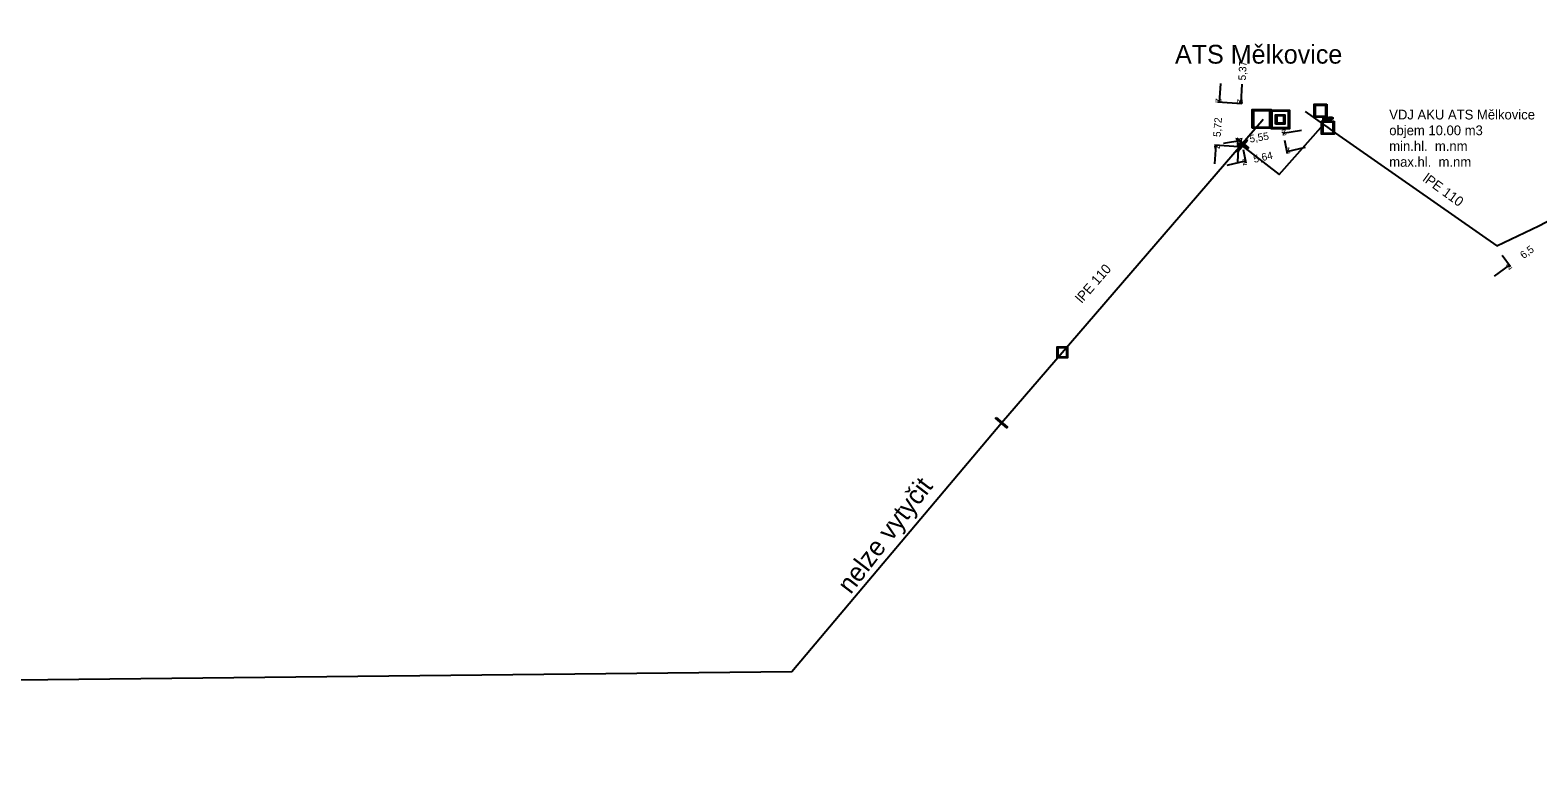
# Model space of a CAD drawing. Extents: x -638315 to -636370, y -1116147 to -1115110.
# Drawn here: x -638032 to -637831.1, y -1115501.1 to -1115402.4 of the extents above; entities that cross this region are included whole.
import ezdxf

# ---------------------------------------------------------------- set-up
doc = ezdxf.new("R2010")
doc.units = 0
for name, color, linetype in [('Default', 7, 'Continuous'), ('VP Kótování', 7, 'Continuous'), ('VP Popis nerozlišený', 7, 'Continuous'), ('VP Vodojem', 7, 'Continuous'), ('VP Vodojem - popis', 7, 'Continuous'), ('VP Čerpací stanice', 7, 'Continuous'), ('VP Řad', 7, 'Continuous'), ('VP Řad - popis', 7, 'Continuous'), ('VP Šachta', 7, 'Continuous'), ('VP Šoupě', 7, 'Continuous')]:
    doc.layers.add(name, color=color, linetype=linetype)

msp = doc.modelspace()

# ---------------------------------------------------------------- linework, layer by layer
at = {"layer": 'Default'}
for points in [[(-637859.55, -1115414.05), (-637859.5, -1115414.05), (-637859.48, -1115414.05), (-637859.45, -1115414.06), (-637859.43, -1115414.07), (-637859.4, -1115414.09), (-637859.39, -1115414.11), (-637859.38, -1115414.14), (-637859.38, -1115414.17), (-637859.38, -1115414.23), (-637859.41, -1115414.26), (-637859.45, -1115414.3), (-637859.54, -1115414.3)], [(-637859.54, -1115414.25), (-637859.48, -1115414.25), (-637859.46, -1115414.23), (-637859.44, -1115414.21), (-637859.44, -1115414.17), (-637859.44, -1115414.15), (-637859.45, -1115414.13), (-637859.46, -1115414.11), (-637859.49, -1115414.1), (-637859.5, -1115414.1), (-637859.54, -1115414.1)], [(-637859.07, -1115414.39), (-637859.1, -1115414.35), (-637859.11, -1115414.33), (-637859.13, -1115414.31), (-637859.14, -1115414.3), (-637859.16, -1115414.29), (-637859.17, -1115414.29), (-637859.18, -1115414.28), (-637859.2, -1115414.28)], [(-637859.14, -1115414.24), (-637859.1, -1115414.24), (-637859.08, -1115414.23), (-637859.06, -1115414.22), (-637859.05, -1115414.2), (-637859.04, -1115414.19), (-637859.04, -1115414.16), (-637859.04, -1115414.13), (-637859.06, -1115414.11), (-637859.08, -1115414.09), (-637859.13, -1115414.09)], [(-637859.13, -1115414.05), (-637859.08, -1115414.05), (-637859.05, -1115414.06), (-637859.02, -1115414.07), (-637859, -1115414.1), (-637858.98, -1115414.13), (-637858.98, -1115414.16), (-637858.98, -1115414.21), (-637859.01, -1115414.24), (-637859.04, -1115414.27), (-637859.1, -1115414.28), (-637859.08, -1115414.29), (-637859.07, -1115414.3), (-637859.04, -1115414.32), (-637859.02, -1115414.36)], [(-637858.58, -1115414.05), (-637858.54, -1115414.05), (-637858.52, -1115414.05), (-637858.49, -1115414.06), (-637858.46, -1115414.07), (-637858.44, -1115414.09), (-637858.43, -1115414.11), (-637858.42, -1115414.14), (-637858.42, -1115414.17), (-637858.42, -1115414.23), (-637858.45, -1115414.26), (-637858.49, -1115414.3), (-637858.58, -1115414.3)], [(-637858.58, -1115414.25), (-637858.52, -1115414.25), (-637858.5, -1115414.23), (-637858.48, -1115414.21), (-637858.48, -1115414.17), (-637858.48, -1115414.15), (-637858.49, -1115414.13), (-637858.5, -1115414.11), (-637858.52, -1115414.1), (-637858.54, -1115414.1), (-637858.58, -1115414.1)]]:
    msp.add_open_spline(points, degree=3, dxfattribs=at)
at = {"layer": 'VP Kótování'}
for points in [[(-637873.39, -1115409.57), (-637873.57, -1115412.06)], [(-637870.56, -1115409.63), (-637870.69, -1115412.13)], [(-637870.58, -1115412.27), (-637873.81, -1115412.04)], [(-637870.72, -1115412.12), (-637870.94, -1115412.11)], [(-637870.57, -1115417.02), (-637870.6, -1115416.85)], [(-637865.09, -1115416.14), (-637865.12, -1115415.97)], [(-637862.61, -1115415.81), (-637865.08, -1115416.21)], [(-637870.98, -1115417.98), (-637874.22, -1115417.75)], [(-637874.15, -1115420.26), (-637873.97, -1115417.77)], [(-637873.02, -1115417.49), (-637870.56, -1115417.1)], [(-637870.99, -1115417.49), (-637871.21, -1115417.48)], [(-637871.08, -1115419.99), (-637870.96, -1115417.49)], [(-637870.4, -1115418.35), (-637870.01, -1115420.12)], [(-637864.9, -1115417.12), (-637864.51, -1115418.88)], [(-637862.12, -1115418.09), (-637864.56, -1115418.64)], [(-637872.5, -1115420.42), (-637870.06, -1115419.87)], [(-637835.87, -1115432.44), (-637834.75, -1115433.94)], [(-637836.91, -1115435.24), (-637834.9, -1115433.74)]]:
    msp.add_lwpolyline(points, dxfattribs=at)
at = {"layer": 'VP Vodojem'}
for points in [[(-637866.7, -1115415.59), (-637866.7, -1115413.09), (-637864.2, -1115413.09), (-637864.2, -1115415.59), (-637866.7, -1115415.59)], [(-637864.36, -1115415.43), (-637864.36, -1115413.24), (-637866.55, -1115413.24), (-637866.55, -1115415.43), (-637864.36, -1115415.43)], [(-637866.08, -1115414.96), (-637866.08, -1115413.71), (-637864.83, -1115413.71), (-637864.83, -1115414.96), (-637866.08, -1115414.96)], [(-637864.98, -1115414.81), (-637864.98, -1115413.87), (-637865.92, -1115413.87), (-637865.92, -1115414.81), (-637864.98, -1115414.81)]]:
    msp.add_lwpolyline(points, dxfattribs=at)
at = {"layer": 'VP Čerpací stanice'}
for points in [[(-637869.17, -1115415.52), (-637869.17, -1115413.02), (-637866.67, -1115413.02), (-637866.67, -1115415.52), (-637869.17, -1115415.52)], [(-637866.82, -1115415.36), (-637866.82, -1115413.17), (-637869.01, -1115413.17), (-637869.01, -1115415.36), (-637866.82, -1115415.36)]]:
    msp.add_lwpolyline(points, dxfattribs=at)
at = {"layer": 'VP Řad'}
for points in [[(-637862.11, -1115413.29), (-637859.7, -1115414.99), (-637859.09, -1115415.42), (-637858.07, -1115416.16), (-637836.57, -1115431.19), (-637830.98, -1115428.5), (-637797.63, -1115410.95), (-637792.98, -1115408.94), (-637778.14, -1115402.44)], [(-638304.3, -1115501.13), (-638261.05, -1115491.44), (-637930.52, -1115487.91), (-637902.6, -1115454.75), (-637894.49, -1115445.38), (-637870.67, -1115417.73), (-637870.49, -1115417.51), (-637870.48, -1115417.5), (-637868.2, -1115414.86), (-637868.12, -1115414.77), (-637867.73, -1115414.32)], [(-637870.67, -1115417.73), (-637870.51, -1115417.86), (-637865.57, -1115421.67), (-637859.7, -1115414.99)]]:
    msp.add_lwpolyline(points, dxfattribs=at)
at = {"layer": 'VP Šachta'}
for points in [[(-637859.23, -1115412.31), (-637859.23, -1115414.05), (-637860.93, -1115414.05), (-637860.93, -1115412.31), (-637859.23, -1115412.31)], [(-637860.78, -1115412.46), (-637860.78, -1115413.91), (-637859.38, -1115413.91), (-637859.38, -1115412.46), (-637860.78, -1115412.46)], [(-637858.24, -1115414.55), (-637858.24, -1115416.29), (-637859.94, -1115416.29), (-637859.94, -1115414.55), (-637858.24, -1115414.55)], [(-637859.79, -1115414.7), (-637859.79, -1115416.15), (-637858.39, -1115416.15), (-637858.39, -1115414.7), (-637859.79, -1115414.7)], [(-637859.71, -1115414.48), (-637859.71, -1115414.05), (-637859.55, -1115414.05)], [(-637859.54, -1115414.3), (-637859.65, -1115414.3), (-637859.65, -1115414.48), (-637859.71, -1115414.48)], [(-637859.54, -1115414.1), (-637859.65, -1115414.1), (-637859.65, -1115414.25)], [(-637859.65, -1115414.25), (-637859.54, -1115414.25)], [(-637859.32, -1115414.48), (-637859.32, -1115414.05), (-637859.13, -1115414.05)], [(-637859.2, -1115414.28), (-637859.27, -1115414.28), (-637859.27, -1115414.48), (-637859.32, -1115414.48)], [(-637859.13, -1115414.09), (-637859.27, -1115414.09), (-637859.27, -1115414.24)], [(-637859.27, -1115414.24), (-637859.14, -1115414.24)], [(-637859.02, -1115414.36), (-637858.94, -1115414.48), (-637859.02, -1115414.48), (-637859.07, -1115414.39)], [(-637858.89, -1115414.48), (-637858.89, -1115414.05), (-637858.83, -1115414.05), (-637858.83, -1115414.48), (-637858.89, -1115414.48)], [(-637858.74, -1115414.48), (-637858.74, -1115414.05), (-637858.58, -1115414.05)], [(-637858.58, -1115414.3), (-637858.69, -1115414.3), (-637858.69, -1115414.48), (-637858.74, -1115414.48)], [(-637858.58, -1115414.1), (-637858.69, -1115414.1), (-637858.69, -1115414.25)], [(-637858.69, -1115414.25), (-637858.58, -1115414.25)], [(-637893.78, -1115444.65), (-637893.78, -1115446.1), (-637895.19, -1115446.1), (-637895.19, -1115444.65), (-637893.78, -1115444.65)], [(-637895.07, -1115444.78), (-637895.07, -1115445.98), (-637893.9, -1115445.98), (-637893.9, -1115444.78), (-637895.07, -1115444.78)]]:
    msp.add_lwpolyline(points, dxfattribs=at)
at = {"layer": 'VP Šoupě'}
for points in [[(-637871.21, -1115416.82), (-637869.69, -1115418.11), (-637869.77, -1115418.21), (-637871.29, -1115416.91), (-637871.21, -1115416.82)], [(-637869.82, -1115417.14), (-637871.11, -1115418.67), (-637871.21, -1115418.59), (-637869.92, -1115417.06), (-637869.82, -1115417.14)], [(-637903.32, -1115454.05), (-637901.81, -1115455.36), (-637901.89, -1115455.45), (-637903.4, -1115454.14), (-637903.32, -1115454.05)]]:
    msp.add_lwpolyline(points, dxfattribs=at)

# ---------------------------------------------------------------- texts
at = {"layer": 'VP Kótování'}
for s, rotation, p in [('5,37', 87.1258, (-637870.04, -1115409.16)), ('z', 265.9452, (-637874.03, -1115411.52)), ('z', 267.1258, (-637871.16, -1115411.6)), ('5,72', 85.9452, (-637873.39, -1115416.7)), ('z', 9.1572, (-637870.97, -1115417.67)), ('5,55', 9.1572, (-637869.47, -1115417.43)), ('z', 189.1572, (-637864.66, -1115415.64)), ('z', 85.9452, (-637873.51, -1115418.3)), ('z', 87.1258, (-637870.48, -1115418.01)), ('5,64', 12.6221, (-637868.91, -1115420.13)), ('z', 192.6221, (-637864.18, -1115418.04)), ('z', 12.6221, (-637870.44, -1115420.47)), ('6,5', 36.7398, (-637833.02, -1115432.96)), ('z', 36.7398, (-637835, -1115434.44))]:
    msp.add_text(s, height=1, rotation=rotation, dxfattribs=at).set_placement(p)
at = {"layer": 'VP Popis nerozlišený'}
msp.add_text('ATS Mělkovice', height=2.5, dxfattribs=at).set_placement((-637879.47, -1115406.9))
msp.add_text('nelze vytyčit', height=2.5, rotation=52.6182, dxfattribs=at).set_placement((-637922.68, -1115477.71))
at = {"layer": 'VP Vodojem - popis'}
for s, p in [('VDJ AKU ATS Mělkovice', (-637850.92, -1115414.34)), ('objem 10.00 m3', (-637850.92, -1115416.44)), ('min.hl.  m.nm', (-637850.92, -1115418.54)), ('max.hl.  m.nm', (-637850.92, -1115420.64))]:
    msp.add_text(s, height=1.3, dxfattribs=at).set_placement(p)
at = {"layer": 'VP Řad - popis'}
for rotation, p in [(324.1209, (-637846.56, -1115422.46)), (48.8938, (-637891.88, -1115438.91))]:
    msp.add_text('lPE 110', height=1.3, rotation=rotation, dxfattribs=at).set_placement(p)

doc.saveas('drawing.dxf')
